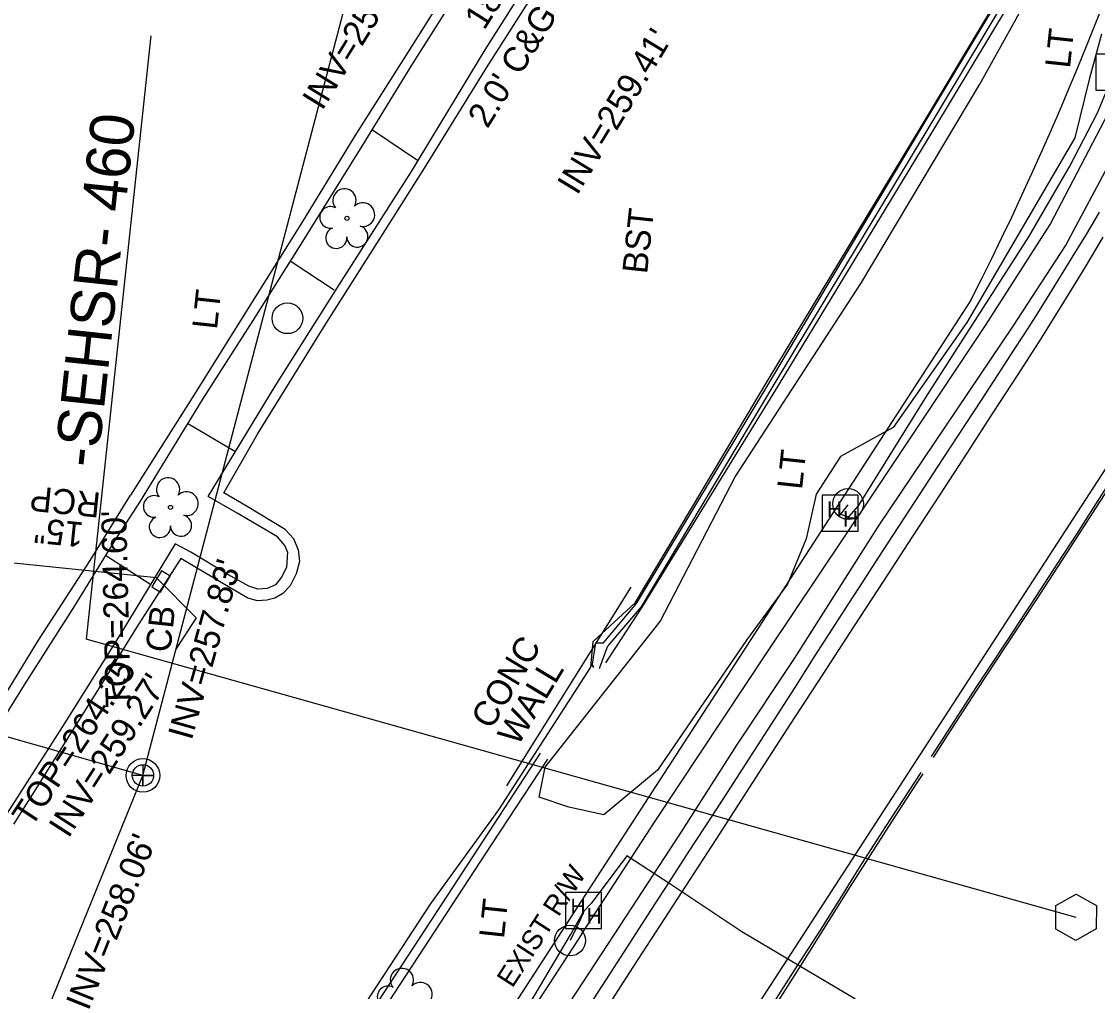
# Model space of a CAD drawing. Extents: x 2100323 to 2109811, y 740376 to 749755.
# Drawn here: x 2105735.6 to 2105907.6, y 742428.5 to 742583.6 of the extents above; entities that cross this region are included whole.
import ezdxf

# ---------------------------------------------------------------- set-up
doc = ezdxf.new("R2010")
doc.units = 0
for name, color, linetype in [('CTL GPS Vertical CELL', 7, 'Continuous'), ('Exist Building', 7, 'Continuous'), ('Exist Building Text', 7, 'Continuous'), ('Exist Horizontal Alignment', 7, 'Continuous'), ('Exist Horizontal Baseline Alignment Station Label', 7, 'Continuous'), ('Exist Other Culture Area Outline', 7, 'Continuous'), ('Exist Other Culture Fence Line', 7, 'Continuous'), ('Exist Right of Way Line', 7, 'Continuous'), ('Exist Right of Way Line Text', 7, 'Continuous'), ('Exist Roads Curbs', 7, 'Continuous'), ('Exist Roads EOP', 7, 'Continuous'), ('Exist Roads EOP Other', 7, 'Continuous'), ('Exist Roads EOP Other Text', 7, 'Continuous'), ('Exist Structure Minor Catch Basin', 7, 'Continuous'), ('Exist Structure Minor Catch Basin Text', 7, 'Continuous'), ('Exist Structure Minor Catch Basin Top Elevation', 7, 'Continuous'), ('Exist Structure Minor Pipes RCP 15 Inch', 7, 'Continuous'), ('Exist Structure Minor Pipes RCP 15 Inch Invert', 7, 'Continuous'), ('Exist Structure Minor Pipes RCP 15 Inch Leader', 7, 'Continuous'), ('Exist Structure Minor Pipes RCP 15 Inch Text', 7, 'Continuous'), ('Exist Structure Minor Pipes RCP 18 Inch Invert', 7, 'Continuous'), ('Exist Structure Minor Pipes RCP 18 Inch Text', 7, 'Continuous'), ('Exist Utilities Other Pole CELL', 7, 'Continuous'), ('Exist Utilities Other Pole Text', 7, 'Continuous'), ('Exist Utilities Power Hand Hole CELL', 7, 'Continuous'), ('Exist Utilities Power UG Cable SUE LOS B', 7, 'Continuous'), ('Exist Utilities Sanitary Sewer Manhole CELL', 7, 'Continuous'), ('Exist Utilities Sanitary Sewer Manhole Text', 7, 'Continuous'), ('Exist Utilities Sanitary Sewer UG Line', 7, 'Continuous'), ('Exist Utilities Sanitary Sewer UG Line Invert Elevation', 7, 'Continuous'), ('Exist Vegetation Tree CELL', 7, 'Continuous'), ('Exist Vegetation Woods Line', 7, 'Continuous')]:
    doc.layers.add(name, color=color, linetype=linetype)

msp = doc.modelspace()

# ---------------------------------------------------------------- linework, layer by layer
at = {"layer": 'CTL GPS Vertical CELL'}
msp.add_line((2105904.19, 742440.35), (2105904.19, 742440.35), dxfattribs=at)
msp.add_lwpolyline([(2105900.96, 742442.22), (2105904.21, 742444.03), (2105907.46, 742442.24), (2105907.41, 742438.52), (2105904.16, 742436.63), (2105900.96, 742438.44)], close=True, dxfattribs=at)
at = {"layer": 'Exist Building'}
for points in [[(2105926.67, 742716.22), (2105918.98, 742681.17), (2105909.46, 742638.52), (2105901.01, 742600.86), (2105900.94, 742600.74), (2105880.81, 742566.97), (2105855.88, 742525.54), (2105834.63, 742490.03), (2105829.31, 742483.75)], [(2105828.63, 742484.23), (2105833.91, 742490.53), (2105855.24, 742525.98), (2105880.05, 742567.56), (2105899.65, 742600.27), (2105898.85, 742600.81), (2105899.08, 742601.7), (2105899.23, 742602.2), (2105900.34, 742602.02), (2105908.75, 742638.65), (2105917.96, 742681.48), (2105925.55, 742715.38)], [(2105826.99, 742480.29), (2105827.08, 742480.49), (2105826.82, 742480.54), (2105827.37, 742484.23), (2105828.63, 742484.23)], [(2105827.97, 742480.12), (2105828.05, 742480.28), (2105829.31, 742483.75)], [(2105670.98, 742240.15), (2105682.89, 742258.66), (2105692.8, 742273.74), (2105709.7, 742299.48), (2105723.54, 742320.83), (2105738.21, 742343.59), (2105757.16, 742372.53), (2105770.97, 742393.51), (2105781.47, 742409.84), (2105802.03, 742441.27), (2105818.56, 742466.6)]]:
    msp.add_lwpolyline(points, dxfattribs=at)
at = {"layer": 'Exist Horizontal Alignment'}
msp.add_line((2105914.81, 742521.27), (2105659.06, 742126.9), dxfattribs=at)
at = {"layer": 'Exist Horizontal Baseline Alignment Station Label'}
for p in [(2105756.26, 742581.31), (2105904.19, 742440.35)]:
    msp.add_line(p, (2105745.92, 742484.81), dxfattribs=at)
at = {"layer": 'Exist Other Culture Area Outline'}
for points in [[(2105798.87, 742561.4), (2105791.71, 742566.22)], [(2105785.58, 742540.65), (2105778.68, 742545.16)], [(2105769.68, 742514.82), (2105762.24, 742519.21)], [(2105756.09, 742493.64), (2105749.14, 742498.09)]]:
    msp.add_lwpolyline(points, dxfattribs=at)
at = {"layer": 'Exist Other Culture Fence Line'}
for points in [[(2105829, 742481.06), (2105834.79, 742489.96), (2105856.6, 742525.42), (2105881.45, 742566.33), (2105902.33, 742601.12), (2105910.66, 742637.84), (2105919.68, 742680.55), (2105928.01, 742716.47)], [(2105598.74, 742236.53), (2105628.53, 742225.99), (2105656.39, 742215.68), (2105671.05, 742239.06), (2105693.86, 742273.76), (2105715.01, 742305.6), (2105736.43, 742338.64), (2105757.27, 742371), (2105783.06, 742409.27), (2105785.25, 742412.99), (2105810.8, 742452.1), (2105819.72, 742465.67)]]:
    msp.add_lwpolyline(points, dxfattribs=at)
at = {"layer": 'Exist Right of Way Line'}
msp.add_line((2105887.38, 742539.07), (2105671.25, 742205.8), dxfattribs=at)
msp.add_arc((2105435.65, 742769.34), 507.03, 332.9892, 359.839, dxfattribs=at)
at = {"layer": 'Exist Roads Curbs'}
for points in [[(2105754.57, 742506.91), (2105764.56, 742523.23), (2105772.59, 742535.8), (2105780.01, 742547.59), (2105790.01, 742563.68), (2105798, 742576.63), (2105807.31, 742591.41), (2105815, 742603.69), (2105822.83, 742616.41), (2105830.48, 742628.45), (2105843.47, 742649.1), (2105852.44, 742663.29), (2105858.69, 742673.3), (2105860.82, 742676.57), (2105863.29, 742680.07), (2105864.87, 742681.67)], [(2105778.1, 742498.79), (2105777.64, 742499.79), (2105776.49, 742501.22), (2105770.04, 742504.99), (2105765.43, 742507.63), (2105776.12, 742525.27), (2105786.35, 742541.5), (2105797.91, 742559.6), (2105809.7, 742579.08), (2105819.14, 742594.02), (2105829.4, 742610.6), (2105837.65, 742623.63), (2105850.99, 742645.15), (2105860.38, 742660.32), (2105864.95, 742667.45)], [(2105907.88, 742553.13), (2105906.7, 742551.09), (2105905.51, 742549.11), (2105904.12, 742546.84), (2105902.51, 742544.23), (2105900.79, 742541.46), (2105899.07, 742538.7), (2105897.36, 742535.97), (2105895.73, 742533.41), (2105894.2, 742531.03), (2105892.66, 742528.66), (2105890.99, 742526.11), (2105889.1, 742523.24), (2105886.43, 742519.15), (2105882.9, 742513.71), (2105878.31, 742506.69), (2105874.89, 742501.46), (2105872.5, 742497.79), (2105870.18, 742494.22), (2105867.78, 742490.53), (2105865.19, 742486.51), (2105862.28, 742481.96), (2105859.09, 742476.97), (2105855.89, 742471.97), (2105852.72, 742467.03), (2105849.45, 742461.95), (2105845.94, 742456.54), (2105842.29, 742450.92), (2105839.02, 742445.89), (2105836.24, 742441.58), (2105833.75, 742437.71), (2105831.34, 742433.99), (2105828.98, 742430.36), (2105826.41, 742426.42)], [(2105911.23, 742511.86), (2105907.42, 742505.93), (2105902.66, 742498.58), (2105897.8, 742491.13), (2105892.98, 742483.78), (2105888.23, 742476.55), (2105883.6, 742469.42), (2105881.33, 742465.9)], [(2105696.19, 742414.13), (2105707.73, 742432.51), (2105718.2, 742448.94), (2105727.58, 742463.93), (2105736.04, 742477.53), (2105744.08, 742490.14), (2105750.49, 742500.58), (2105754.57, 742506.91)], [(2105778.1, 742498.79), (2105777.92, 742496.27), (2105777.13, 742494.73), (2105776.16, 742493.51), (2105774.82, 742492.94), (2105773.33, 742492.84), (2105771.92, 742493.31), (2105768.68, 742495.1), (2105762.63, 742498.73), (2105760.12, 742500.09), (2105751.62, 742485.99), (2105742.49, 742471.45), (2105733.66, 742457.61), (2105725.62, 742444.93), (2105715.29, 742428.05)], [(2105879.66, 742463.3), (2105878.83, 742462.02), (2105876.92, 742459.07), (2105873.73, 742454.15), (2105868.09, 742445.28), (2105859.79, 742432.13), (2105851.93, 742419.68)]]:
    msp.add_lwpolyline(points, dxfattribs=at)
at = {"layer": 'Exist Roads EOP'}
for points in [[(2105811.87, 742457.54), (2105826.58, 742480.33), (2105826.99, 742484.46), (2105833.69, 742490.64), (2105854.94, 742526.31), (2105879.29, 742566.6), (2105899.41, 742600.2), (2105898.56, 742600.76), (2105899.3, 742602.35), (2105900.27, 742602.32), (2105908.06, 742637.8), (2105917.66, 742681.14), (2105925.4, 742715.53)], [(2105908.45, 742549.1), (2105905.58, 742544.25), (2105902.17, 742538.71), (2105898.58, 742532.99), (2105894.85, 742527.17), (2105890.95, 742521.12), (2105886.81, 742514.73), (2105882.45, 742508.03), (2105877.99, 742501.19), (2105873.43, 742494.23), (2105868.69, 742486.98), (2105863.67, 742479.26), (2105858.49, 742471.26), (2105853.91, 742464.17), (2105850.06, 742458.2), (2105846.58, 742452.8), (2105843.1, 742447.44), (2105839.63, 742442.12), (2105836.18, 742436.8), (2105832.73, 742431.46), (2105829.2, 742425.99)], [(2105909.86, 742510.4), (2105906.67, 742505.43), (2105904.24, 742501.64), (2105901.11, 742496.82), (2105897.05, 742490.6), (2105893.09, 742484.56), (2105890.27, 742480.28), (2105888.29, 742477.29), (2105885.31, 742472.71), (2105881.02, 742466.09)], [(2105879.35, 742463.5), (2105873.72, 742454.88), (2105869.52, 742448.31), (2105866.52, 742443.49), (2105863.25, 742438.29), (2105859.45, 742432.38), (2105855.77, 742426.65)]]:
    msp.add_lwpolyline(points, dxfattribs=at)
at = {"layer": 'Exist Roads EOP Other'}
for points in [[(2105859.15, 742481.73), (2105872.72, 742503.09), (2105894.11, 742534.91), (2105902.49, 742547.72), (2105910.12, 742562.02), (2105917.42, 742577.01), (2105924.25, 742592.75), (2105929.58, 742606.5), (2105934.63, 742621.39), (2105938.39, 742634.25), (2105940.86, 742644.46), (2105943.09, 742654.48), (2105945.83, 742669.61), (2105947.77, 742684.32), (2105948.97, 742694.19), (2105951.52, 742694.05)], [(2105863.86, 742683.17), (2105861.23, 742680.1), (2105858.1, 742675.57), (2105853.85, 742668.74), (2105849.71, 742662.47), (2105839.88, 742646.6), (2105826.68, 742625.7), (2105818.79, 742613.2), (2105808.84, 742596.98), (2105798.01, 742579.76), (2105788.85, 742565.3), (2105780.34, 742551.34), (2105772.73, 742539.21), (2105763.22, 742523.99), (2105752.97, 742507.88)], [(2105779.81, 742499.16), (2105779.08, 742500.88), (2105777.7, 742502.35), (2105771.65, 742506.06), (2105767.9, 742508.25), (2105773.32, 742517.62), (2105784.22, 742535.27), (2105793.11, 742549.28), (2105800.26, 742560.56), (2105809.93, 742576.18), (2105819.04, 742590.52), (2105830.93, 742609.91), (2105837.65, 742620.49), (2105848.12, 742636.91), (2105856.98, 742651.33), (2105866.5, 742667.54), (2105865.3, 742667.65)], [(2105854.82, 742482.79), (2105871.25, 742507.32), (2105889.73, 742535.02), (2105900.03, 742551.14), (2105909.94, 742570.11)], [(2105695.91, 742417.01), (2105704.48, 742430.65), (2105711.62, 742441.9), (2105719.52, 742454.32), (2105728.47, 742468.68), (2105738.3, 742484.69), (2105746.53, 742497.42), (2105752.97, 742507.88)], [(2105779.81, 742499.16), (2105780.02, 742497.24), (2105779.47, 742495.3), (2105778.54, 742493.38), (2105777.34, 742492.13), (2105776.09, 742491.41), (2105774.81, 742491.05), (2105773.29, 742490.99), (2105771.73, 742491.4), (2105768.94, 742493.03), (2105761.02, 742497.74), (2105754.23, 742487.1), (2105748.25, 742477.5), (2105737.23, 742459.9), (2105727.17, 742444.03), (2105716.19, 742426.18)], [(2105813.14, 742461.39), (2105833.06, 742493.14)], [(2105825.17, 742437.69), (2105837.01, 742455.87), (2105854.82, 742482.79)], [(2105823.22, 742426.72), (2105831.32, 742439.1), (2105841.09, 742454), (2105849.93, 742467.9), (2105859.15, 742481.73)], [(2105785.03, 742418.1), (2105801.05, 742442.64), (2105811.87, 742457.54)], [(2105825.17, 742437.69), (2105813.9, 742420.45)]]:
    msp.add_lwpolyline(points, dxfattribs=at)
at = {"layer": 'Exist Structure Minor Catch Basin'}
msp.add_lwpolyline([(2105757.97, 742495.75), (2105756.41, 742493.19), (2105757.77, 742492.37), (2105759.33, 742494.92)], close=True, dxfattribs=at)
at = {"layer": 'Exist Structure Minor Pipes RCP 15 Inch'}
msp.add_line((2105757.13, 742494.66), (2105699.01, 742500.54), dxfattribs=at)
at = {"layer": 'Exist Structure Minor Pipes RCP 15 Inch Leader'}
msp.add_lwpolyline([(2105757.13, 742494.66), (2105763.47, 742488.27), (2105760.22, 742483.23)], dxfattribs=at)
at = {"layer": 'Exist Utilities Other Pole CELL'}
for centre in [(2105778.08, 742536.15), (2105867.73, 742506.45), (2105823.27, 742436.64)]:
    msp.add_circle(centre, 2.46, dxfattribs=at)
at = {"layer": 'Exist Utilities Power Hand Hole CELL'}
for p, q in [((2105866.52, 742504.85), (2105866.52, 742504.85)), ((2105825.5, 742441.32), (2105825.5, 742441.32))]:
    msp.add_line(p, q, dxfattribs=at)
for points in [[(2105907.33, 742572.65), (2105913.08, 742572.65), (2105913.08, 742578.4), (2105907.33, 742578.4), (2105907.33, 742572.65)], [(2105863.57, 742502.12), (2105869.32, 742502.12), (2105869.32, 742507.87), (2105863.57, 742507.87), (2105863.57, 742502.12)], [(2105822.55, 742438.59), (2105828.3, 742438.59), (2105828.3, 742444.34), (2105822.55, 742444.34), (2105822.55, 742438.59)]]:
    msp.add_lwpolyline(points, dxfattribs=at)
at = {"layer": 'Exist Utilities Power UG Cable SUE LOS B'}
for points in [[(2105867.69, 742506.32), (2105866.52, 742504.85), (2105867.87, 742504.41), (2105869.39, 742506.18), (2105880.34, 742523.76), (2105896.61, 742549.18), (2105903.19, 742560.45), (2105907.6, 742569.02), (2105910.28, 742575.38), (2105910.94, 742576.67), (2105911.15, 742577.09)], [(2105874.32, 742369.04), (2105875.2, 742371.15), (2105879.73, 742387.73), (2105884.33, 742406.29), (2105884.14, 742410.4), (2105882.68, 742412.04), (2105868.82, 742427.33), (2105850.72, 742438.03), (2105839.4, 742445.62), (2105832.37, 742450.2), (2105826.65, 742442.55), (2105825.5, 742441.32), (2105824.92, 742440.04), (2105823.27, 742436.64)], [(2105728.59, 742291.06), (2105729.1, 742291.95), (2105741.29, 742309.6), (2105748.6, 742320.64), (2105764.9, 742344.44), (2105775.56, 742363.31), (2105790.07, 742385.94), (2105801.37, 742402.22), (2105815.99, 742425.13), (2105823.36, 742437.54), (2105825.5, 742441.32)]]:
    msp.add_lwpolyline(points, dxfattribs=at)
at = {"layer": 'Exist Utilities Sanitary Sewer Manhole CELL'}
msp.add_lwpolyline([(2105754.97, 742464.76), (2105754.97, 742461.33), (2105754.97, 742463.04), (2105756.68, 742463.04), (2105753.26, 742463.04)], dxfattribs=at)
for radius in [2.69, 1.71]:
    msp.add_circle((2105754.97, 742463.04), radius, dxfattribs=at)
at = {"layer": 'Exist Utilities Sanitary Sewer UG Line'}
for p, q in [((2105754.97, 742463.04), (2105708.12, 742476.3)), ((2105647.5, 742198.64), (2105754.97, 742463.04))]:
    msp.add_line(p, q, dxfattribs=at)
msp.add_lwpolyline([(2105754.97, 742463.04), (2105903.79, 743029.64)], dxfattribs=at)
at = {"layer": 'Exist Vegetation Tree CELL'}
for p, q in [((2105787.59, 742552.13), (2105787.59, 742552.13)), ((2105759.38, 742505.9), (2105759.38, 742505.9))]:
    msp.add_line(p, q, dxfattribs=at)
for centre in [(2105787.59, 742552.13), (2105759.38, 742505.9)]:
    msp.add_circle(centre, 0.326, dxfattribs=at)
for centre, radius, start, end in [((2105787.2, 742555.01), 1.86, 330.1651, 219.7134), ((2105790.14, 742552.72), 1.9, 257.1011, 134.1999), ((2105784.98, 742552.29), 1.73, 62.6636, 279.3457), ((2105785.89, 742549.01), 1.69, 111.5671, 6.231), ((2105789.26, 742549.23), 1.7, 181.2822, 74.56), ((2105759, 742508.78), 1.86, 330.1651, 219.7134), ((2105761.93, 742506.49), 1.9, 257.1011, 134.1999), ((2105756.78, 742506.06), 1.73, 62.6636, 279.3457), ((2105761.06, 742503), 1.7, 181.2822, 74.56), ((2105757.68, 742502.78), 1.69, 111.5671, 6.231), ((2105796.39, 742430.34), 1.86, 330.1651, 219.7134), ((2105794.17, 742427.62), 1.73, 62.6636, 279.3457), ((2105799.33, 742428.05), 1.9, 257.1011, 134.1999)]:
    msp.add_arc(centre, radius, start, end, dxfattribs=at)
at = {"layer": 'Exist Vegetation Woods Line'}
for points in [[(2105837.67, 742487.68), (2105849.66, 742510.81), (2105869.88, 742541.86), (2105888.79, 742573.57), (2105904.62, 742602.1), (2105912.79, 742617.9)], [(2105908.26, 742581.61), (2105906.33, 742574.56), (2105903.97, 742565.02), (2105886.7, 742535.47), (2105874.93, 742518.67), (2105866.54, 742514.06), (2105862.64, 742508.01), (2105861.05, 742500.9), (2105858.03, 742493.65), (2105851.5, 742484.66)], [(2105851.5, 742484.66), (2105837.27, 742463.89), (2105828.68, 742456.74), (2105823.08, 742457.99), (2105818.35, 742459.58), (2105819.29, 742464.37), (2105837.67, 742487.68)]]:
    msp.add_lwpolyline(points, dxfattribs=at)

# ---------------------------------------------------------------- texts
at = {"layer": 'Exist Building Text'}
for s, p in [('CONC', (2105810.65, 742470.22)), ('WALL', (2105814.91, 742467.58))]:
    msp.add_text(s, height=4, rotation=58.923, dxfattribs=at).set_placement(p)
at = {"layer": 'Exist Horizontal Baseline Alignment Station Label'}
msp.add_text('-SEHSR- 460', height=7, rotation=83.8864, dxfattribs=at).set_placement((2105747.73, 742512.13))
at = {"layer": 'Exist Right of Way Line Text'}
msp.add_text('EXIST R/W', height=3.2, rotation=57.0367, dxfattribs=at).set_placement((2105814.05, 742428.93))
at = {"layer": 'Exist Roads EOP Other Text'}
for s, rotation, p in [("2.0' C&G", 58.2607, (2105810.07, 742566.36)), ('BST', 83.8864, (2105835.59, 742543.14))]:
    msp.add_text(s, height=4, rotation=rotation, dxfattribs=at).set_placement(p)
at = {"layer": 'Exist Structure Minor Catch Basin Text'}
msp.add_text('CB', height=4, rotation=83.8864, dxfattribs=at).set_placement((2105759.36, 742482.6))
at = {"layer": 'Exist Structure Minor Catch Basin Top Elevation'}
msp.add_text("TOP=264.25'", height=4, rotation=56.3453, dxfattribs=at).set_placement((2105737.14, 742454.58))
at = {"layer": 'Exist Structure Minor Pipes RCP 15 Inch Invert'}
msp.add_text("INV=259.27'", height=4, rotation=57.2117, dxfattribs=at).set_placement((2105743.05, 742452.87))
at = {"layer": 'Exist Structure Minor Pipes RCP 15 Inch Text'}
for s, p in [('RCP', (2105748.35, 742508.23)), ('15"', (2105745.62, 742503.47))]:
    msp.add_text(s, height=4, rotation=174.2202, dxfattribs=at).set_placement(p)
at = {"layer": 'Exist Structure Minor Pipes RCP 18 Inch Invert'}
for s, rotation, p in [("INV=258.90'", 58.3198, (2105783.64, 742569.23)), ("INV=259.41'", 58.6876, (2105824.42, 742555.69))]:
    msp.add_text(s, height=4, rotation=rotation, dxfattribs=at).set_placement(p)
at = {"layer": 'Exist Structure Minor Pipes RCP 18 Inch Text'}
msp.add_text('18" RCP', height=4, rotation=57.8606, dxfattribs=at).set_placement((2105809.55, 742582.09))
at = {"layer": 'Exist Utilities Other Pole Text'}
for p in [(2105903.2, 742576.02), (2105766.81, 742534.26), (2105860.36, 742508.65), (2105812.7, 742436.84)]:
    msp.add_text('LT', height=4, rotation=83.8864, dxfattribs=at).set_placement(p)
at = {"layer": 'Exist Utilities Power Hand Hole CELL'}
for p in [(2105864.36, 742504.37), (2105866.92, 742502.85), (2105823.34, 742440.84), (2105825.91, 742439.32)]:
    msp.add_text('H', height=2.5, dxfattribs=at).set_placement(p)
at = {"layer": 'Exist Utilities Sanitary Sewer Manhole Text'}
msp.add_text("TOP=264.60'", height=4, rotation=91.347, dxfattribs=at).set_placement((2105753.03, 742473.96))
at = {"layer": 'Exist Utilities Sanitary Sewer UG Line Invert Elevation'}
for s, rotation, p in [("INV=257.83'", 74.2548, (2105762.76, 742468.53)), ("INV=258.06'", 68.2533, (2105746.26, 742425.27))]:
    msp.add_text(s, height=4, rotation=rotation, dxfattribs=at).set_placement(p)

doc.saveas('drawing.dxf')
